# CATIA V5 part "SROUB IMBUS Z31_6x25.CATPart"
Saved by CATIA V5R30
Part number: SROUB IMBUS Z31/6x25
Bounding box of the stored display mesh (mm): x -6 to 25, y -4.99 to 4.99, z -5 to 5
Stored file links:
  C:\Users\ondra\Desktop\PŘÍLOHA P III\CATIA\SROUB IMBUS Z31_6x25.CATPart
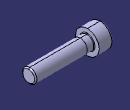
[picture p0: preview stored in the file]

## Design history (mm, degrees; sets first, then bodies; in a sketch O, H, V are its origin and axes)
Set1
  DatumSurface1 to DatumSurface29 "Z31/6x25"
  Join1: Elements (DatumSurface1; DatumSurface2; DatumSurface3; DatumSurface4; DatumSurface5; DatumSurface6; DatumSurface7; DatumSurface8; DatumSurface9; DatumSurface10; DatumSurface11; DatumSurface12; DatumSurface13; DatumSurface14; DatumSurface15; DatumSurface16; DatumSurface17; DatumSurface18; DatumSurface19; DatumSurface20; DatumSurface21; DatumSurface22; DatumSurface23; DatumSurface24; DatumSurface25; DatumSurface26; DatumSurface27; DatumSurface28; DatumSurface29)
Set2 "Geometry Failure"
  Set3 "FaceKO#Z31/6x25#409"
    DatumSurface30 "Sur409_1"
    Circle1 "Crv409_1": stored without definition
    DatumCurve1 "PCrv409_1"
    Circle2 "Crv409_2": stored without definition
    DatumCurve2 "PCrv409_2"
    Circle3 "Crv409_3": stored without definition
    DatumCurve3 "PCrv409_3"
    Circle4 "Crv409_4": stored without definition
    DatumCurve4 "PCrv409_4"
Body1 (main body)
  CloseSurface1: CloseElement Join1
